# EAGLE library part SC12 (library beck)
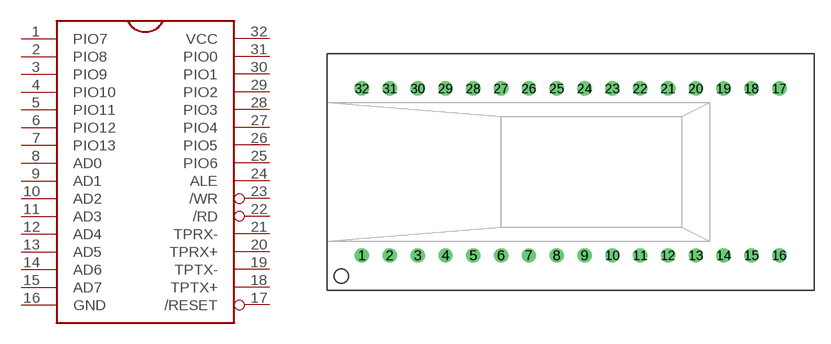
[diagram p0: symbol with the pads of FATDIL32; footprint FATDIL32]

Designator prefix -

## SC12FATDIL32  [FATDIL32]
1  PIO7
2  PIO8
3  PIO9
4  PIO10
5  PIO11
6  PIO12
7  PIO13
8  AD0
9  AD1
10  AD2
11  AD3
12  AD4
13  AD5
14  AD6
15  AD7
16  GND  pwr
17  /RESET
18  TPTX+  out
19  TPTX-  out
20  TPRX+  in
21  TPRX-  in
22  /RD  out
23  /WR  out
24  ALE  out
25  PIO6
26  PIO5
27  PIO4
28  PIO3
29  PIO2
30  PIO1
31  PIO0
32  VCC  pwr

## Footprint FATDIL32 (pad centres in mm)
drill 0.813 round: 1 -19.05,-7.62; 2 -16.51,-7.62; 3 -13.97,-7.62; 4 -11.43,-7.62; 5 -8.89,-7.62; 6 -6.35,-7.62; 7 -3.81,-7.62; 8 -1.27,-7.62; 9 1.27,-7.62; 10 3.81,-7.62; 11 6.35,-7.62; 12 8.89,-7.62; 13 11.43,-7.62; 14 13.97,-7.62; 15 16.51,-7.62; 16 19.05,-7.62; 17 19.05,7.62; 18 16.51,7.62; 19 13.97,7.62; 20 11.43,7.62; 21 8.89,7.62; 22 6.35,7.62; 23 3.81,7.62; 24 1.27,7.62; 25 -1.27,7.62; 26 -3.81,7.62; 27 -6.35,7.62; 28 -8.89,7.62; 29 -11.43,7.62; 30 -13.97,7.62; 31 -16.51,7.62; 32 -19.05,7.62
